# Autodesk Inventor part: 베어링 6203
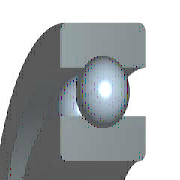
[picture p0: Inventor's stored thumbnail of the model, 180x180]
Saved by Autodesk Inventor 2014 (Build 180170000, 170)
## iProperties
IsCustomPart: 1
Created: 2015-09
Part Number: 베어링 6203
Material: 강철, 연강
Description: 깊은 그루브 볼 베어링
Document SubType Name: Modeling
Standard: KS B 2023
Standards Organization: KS
Language: ko-KR
Size Designation: 6203 - 17 x 40 x 12
Categories: <MemberInstance><Categories><Category DisplayName="샤프트 부품" InternalName="7f7aeb1f-a693-4053-b835-cee3144e0d98" Mnemonic="SHFT"><Category DisplayName="베어링" Inter
Density: 7.86 g/cm^3
Mass: 64.9809 g
Surface Area: 64.3582 cm^2
Volume: 8.26729 cm^3
Appearance: 노란색
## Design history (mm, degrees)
sketch "스케치" dims "d0" = 5.98 (= -0.26 x WD + 0.26 x BD)
  geometry: L1 (3.01, 14.25)-(8.99, 14.25); L2 (6, 14.25)-(6, 11.26); L3 (6, 14.25)-(6, 17.24); L4 (3.778, 12.249)-(0, 12.249); L5 (0, 8.5)-(12, 8.5); L6 (3.778, 16.251)-(0, 16.251); L7 (0, 20)-(12, 20); L8 (12, 8.5)-(12, 12.249); L9 (8.222, 12.249)-(12, 12.249); L10 (8.222, 16.251)-(12, 16.251); L11 (12, 20)-(12, 16.251); L12 (-1.4, 0)-(8.4, 0) reference; L13 (0, -0.3)-(0, 5.3) reference
  constraints: 22 end point, 4 point on line, 2 collinear, 2 perpendicular, 2 symmetric about line, 1 midpoint, 1 parallel, 14 other
  dimensions: "d9" = 17 diameter of L5 L12 (= WD); "d11" = 40 diameter of L7 L12 (= BD); "d12" = 12 distance between parallel lines of L8 L13 (= KB); "d13" = 24.498 diameter of L9 L12 (= 0.326 x BD + 0.674 x WD)
revolve "본체" stored, may be unused: angle "d6" = 90 deg
revolve "볼" stored, may be unused: angle "d7" = 90 deg
pattern_circular "IDS_ARRAYBALL[SIMPL:T]" dims angle "d3" = 360 deg
body "Solid1"
fillet "모깎기1" dims "d1" = 0.6 (= KRS)
other parameters: "WD" = 17 [user parameter; used in 5 equation terms], "BD" = 40 [user parameter; used in 5 equation terms], "KB" = 12 [user parameter; used in 1 equation term], "KRS" = 0.6 [user parameter; used in 1 equation term], "d4" = 0, "d5" = 0, "d8" = 0, "d14" = 0, "d15" = 0, "BBA" = 0 [user parameter], "BC0" = 4750000 [user parameter], "BC" = 9560000 [user parameter], "WR" = 8.5 (= 0.5 x WD) [user parameter]
